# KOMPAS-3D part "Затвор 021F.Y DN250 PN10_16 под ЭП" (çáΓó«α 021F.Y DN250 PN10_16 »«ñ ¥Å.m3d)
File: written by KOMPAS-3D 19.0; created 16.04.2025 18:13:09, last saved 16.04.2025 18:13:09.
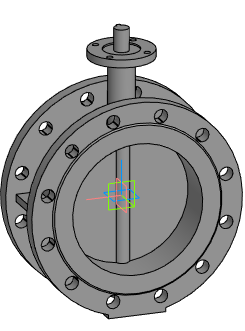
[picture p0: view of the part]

Document properties: Автор: Евгений; Полное имя файла: E:\Dendor Работа Сачек\3D для проекитирвщиков\1.6 Тип 021F.Y Затвор дисковый поворотный фланцевый\stp_Тип 021F.Y Затвор  DN40 PN10_16 под ЭП\Затвор 021F.Y DN250 PN10_16 под ЭП.m3d

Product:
- Part/product: Затвор 021F.Y DN250 PN10_16 под ЭП

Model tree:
1. Операция без истории:1  (labels: Затвор 021F.Y DN250 PN10_16 под ЭП)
